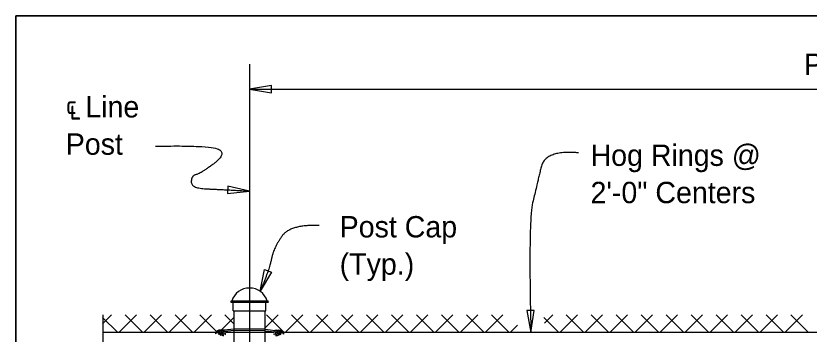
# Model space of a CAD drawing. Extents: x 0 to 41.2, y 0 to 26.
# Drawn here: x 0 to 7.49, y 22.96 to 25.96 of the extents above; entities that cross this region are included whole.
import ezdxf

# ---------------------------------------------------------------- set-up
doc = ezdxf.new("R2010")
doc.units = 0
for name, color, linetype in [('ActivePts-ConstElements', 7, 'Continuous'), ('CL_Major', 7, 'Continuous'), ('Dimension', 7, 'Continuous'), ('Miscellaneous', 7, 'Continuous'), ('Miscellaneous1', 7, 'Continuous'), ('SteelMisc', 7, 'Continuous'), ('SteelMisc_h', 7, 'Continuous'), ('TextStructures', 7, 'Continuous')]:
    doc.layers.add(name, color=color, linetype=linetype)

msp = doc.modelspace()

# ---------------------------------------------------------------- linework, layer by layer
at = {"layer": 'ActivePts-ConstElements'}
msp.add_lwpolyline([(0, 0), (41.2106, 0), (41.2106, 25.96), (0, 25.96)], close=True, dxfattribs=at)
at = {"layer": 'CL_Major'}
msp.add_line((2.2062, 25.5043), (2.2062, 14.6639), dxfattribs=at)
at = {"layer": 'Dimension'}
msp.add_line((2.2062, 25.2672), (22.2062, 25.2672), dxfattribs=at)
for points in [[(2.2062, 25.2672), (2.4145, 25.2319), (2.4145, 25.3025)], [(2.2062, 24.3062), (2.0002, 24.3528), (1.9964, 24.2823)], [(2.3061, 23.3596), (2.3482, 23.5666), (2.414, 23.5412)], [(4.8623, 22.9695), (4.8931, 23.1785), (4.8225, 23.177)]]:
    msp.add_lwpolyline(points, close=True, dxfattribs=at)
msp.add_lwpolyline([(0.8194, 23.1382), (0.8194, 21.1819), (0.9227, 21.1819), (0.8194, 21.1369), (0.716, 21.0919), (0.8194, 21.0919), (0.8194, 20.1983)], dxfattribs=at)
for points in [[(1.3166, 24.7299), (1.8624, 24.7397), (1.9848, 24.6508), (1.7406, 24.4695), (1.6558, 24.4512), (1.6558, 24.3333), (1.9338, 24.321), (2.2061, 24.3061)], [(5.3115, 24.667), (4.9982, 24.6953), (4.9198, 24.3731), (4.8367, 24.0148), (4.8622, 22.9695)], [(2.8646, 23.9801), (2.5898, 23.9929), (2.4301, 23.7626), (2.3965, 23.5753), (2.3061, 23.3596)]]:
    msp.add_open_spline(points, degree=2, dxfattribs=at)
at = {"layer": 'Miscellaneous'}
for p, q in [((0.9027, 23.1361), (0.8192, 23.0527)), ((0.9619, 22.9695), (0.8192, 23.1121)), ((1.1384, 23.1361), (0.9717, 22.9695)), ((1.1976, 22.9695), (1.0309, 23.1361)), ((1.3741, 23.1361), (1.2074, 22.9695)), ((1.4333, 22.9695), (1.2666, 23.1361)), ((1.6098, 23.1361), (1.4431, 22.9695)), ((1.669, 22.9695), (1.5023, 23.1361)), ((1.8455, 23.1361), (1.6788, 22.9695)), ((1.8932, 22.981), (1.738, 23.1361)), ((2.0603, 23.1153), (1.9381, 22.993)), ((2.0603, 23.0495), (1.9737, 23.1361)), ((2.4746, 23.1361), (2.352, 23.0136)), ((2.5338, 22.9695), (2.3671, 23.1361)), ((2.7103, 23.1361), (2.5436, 22.9695)), ((2.7695, 22.9695), (2.6028, 23.1361)), ((2.946, 23.1361), (2.7793, 22.9695)), ((3.0052, 22.9695), (2.8385, 23.1361)), ((3.1817, 23.1361), (3.015, 22.9695)), ((3.2409, 22.9695), (3.0742, 23.1361)), ((3.4174, 23.1361), (3.2507, 22.9695)), ((3.4766, 22.9695), (3.3099, 23.1361)), ((3.6531, 23.1361), (3.4864, 22.9695)), ((3.7123, 22.9695), (3.5456, 23.1361)), ((3.8888, 23.1361), (3.7221, 22.9695)), ((3.948, 22.9695), (3.7813, 23.1361)), ((4.1245, 23.1361), (3.9578, 22.9695)), ((4.1837, 22.9695), (4.017, 23.1361)), ((4.3602, 23.1361), (4.1935, 22.9695)), ((4.4194, 22.9695), (4.2527, 23.1361)), ((4.5959, 23.1361), (4.4292, 22.9695)), ((4.6551, 22.9695), (4.4884, 23.1361)), ((5.1265, 22.9695), (4.9846, 23.1113)), ((5.0673, 23.1361), (4.991, 23.0599)), ((5.303, 23.1361), (5.1363, 22.9695)), ((5.3622, 22.9695), (5.1955, 23.1361)), ((5.5387, 23.1361), (5.372, 22.9695)), ((5.5979, 22.9695), (5.4312, 23.1361)), ((5.7744, 23.1361), (5.6077, 22.9695)), ((5.8336, 22.9695), (5.6669, 23.1361)), ((6.0101, 23.1361), (5.8434, 22.9695)), ((6.0693, 22.9695), (5.9026, 23.1361)), ((6.2458, 23.1361), (6.0791, 22.9695)), ((6.305, 22.9695), (6.1383, 23.1361)), ((6.4815, 23.1361), (6.3148, 22.9695)), ((6.5407, 22.9695), (6.374, 23.1361)), ((6.7172, 23.1361), (6.5505, 22.9695)), ((6.7764, 22.9695), (6.6097, 23.1361)), ((6.9529, 23.1361), (6.7862, 22.9695)), ((7.0121, 22.9695), (6.8455, 23.1361)), ((7.1886, 23.1361), (7.0219, 22.9695)), ((7.2478, 22.9695), (7.0812, 23.1361)), ((7.4243, 23.1361), (7.2576, 22.9695)), ((7.4835, 22.9695), (7.3169, 23.1361)), ((4.7358, 23.0403), (4.6649, 22.9695)), ((1.9047, 22.9695), (1.9002, 22.9739)), ((4.8908, 22.9695), (4.8908, 22.9695))]:
    msp.add_line(p, q, dxfattribs=at)
at = {"layer": 'Miscellaneous1'}
msp.add_lwpolyline([(0, 25.96), (41.2106, 25.96), (41.2106, 0), (0, 0)], close=True, dxfattribs=at)
at = {"layer": 'SteelMisc'}
for p, q in [((2.3786, 23.2681), (2.034, 23.2681)), ((2.034, 23.2559), (2.3786, 23.2559)), ((2.0522, 23.1761), (2.0522, 23.2559)), ((2.3603, 23.1761), (2.3603, 23.2559)), ((2.0522, 23.1761), (2.3603, 23.1761)), ((2.0603, 17.5309), (2.0603, 23.1761)), ((2.352, 17.5309), (2.352, 23.1761)), ((2.0608, 23.0038), (1.9665, 22.9926)), ((2.0608, 22.9892), (1.9687, 22.9798)), ((2.352, 23.0021), (2.0608, 23.0038)), ((2.352, 22.9876), (2.0608, 22.9892)), ((2.352, 23.0021), (2.4469, 22.991)), ((1.8859, 22.9695), (0.8192, 22.9695)), ((1.9096, 22.9695), (1.8943, 22.9695)), ((2.0603, 22.9695), (1.9799, 22.9695)), ((2.352, 22.9876), (2.4446, 22.978)), ((2.4342, 22.9695), (2.352, 22.9695)), ((2.5172, 22.9695), (2.5041, 22.9695)), ((11.923, 22.9695), (2.5271, 22.9695))]:
    msp.add_line(p, q, dxfattribs=at)
for centre, start, end in [((2.034, 23.2618), 91.1647, 268.8353), ((2.3783, 23.2618), 271.1647, 88.8353)]:
    msp.add_arc(centre, 0.00613, start, end, dxfattribs=at)
for centre, major_axis, ratio, start_param, end_param in [((2.2055, 23.227), (-0.1711, 0), 0.957868, 3.394611, 6.030583), ((1.9209, 22.957), (0.0373, 0), 0.957868, 1.486836, 3.108042), ((1.9333, 22.9714), (0.023, 0), 0.957868, 1.29026, 2.970541), ((1.9521, 22.9661), (0.0295, 0), 0.957868, 1.220941, 4.039556), ((1.9656, 22.9678), (-0.0303, -0.0108), 0.724765, 4.35367, 6.324556), ((2.4482, 22.9661), (0.0303, -0.0108), 0.724765, 6.241815, 8.212701), ((2.4617, 22.9643), (-0.0295, 0), 0.957868, 2.243629, 5.062245), ((2.4804, 22.9697), (-0.023, 0), 0.957868, 3.312645, 4.992926), ((2.4929, 22.9552), (-0.0373, 0), 0.957868, 3.175144, 4.79635), ((1.942, 22.9173), (-0.0724, 0), 0.957868, 5.162149, 5.652106), ((1.9345, 22.9689), (-0.0249, 0), 0.957868, 6.009018, 7.089857), ((1.9554, 22.9592), (0.0206, -0.0021), 0.798607, 3.333154, 5.220153), ((1.9623, 22.9638), (-0.0139, 0), 0.957868, 5.22362, 6.905413), ((1.9566, 22.9614), (-0.00795, 0), 0.957868, 6.140374, 9.314262), ((1.9706, 22.9549), (-0.0259, 0), 0.957868, 4.777514, 5.62749), ((1.9549, 22.9672), (0.0119, 0), 0.957868, 5.725876, 7.416677), ((1.9549, 22.9672), (0.0119, 0), 0.957868, 5.639684, 5.723117), ((1.9551, 22.966), (0.0251, 0), 0.957868, 5.531357, 6.227833), ((1.9551, 22.966), (0.0251, 0), 0.957868, 0.407687, 0.609214), ((2.4586, 22.9642), (-0.0251, 0), 0.957868, 0.055352, 0.751829), ((2.4586, 22.9642), (-0.0251, 0), 0.957868, 5.673972, 5.875498), ((2.4431, 22.9532), (0.0259, 0), 0.957868, 0.655696, 1.505671), ((2.4589, 22.9654), (-0.0119, 0), 0.957868, 5.149694, 6.840495), ((2.4589, 22.9654), (-0.0119, 0), 0.957868, 0.560069, 0.643501), ((2.4572, 22.9596), (0.00795, 0), 0.957868, 3.252108, 6.425997), ((2.4583, 22.9575), (-0.0206, -0.0021), 0.798607, 1.063032, 2.950031), ((2.4515, 22.962), (0.0139, 0), 0.957868, 5.660958, 7.342751), ((2.4793, 22.9671), (0.0249, 0), 0.957868, 5.476514, 6.557353), ((2.4718, 22.9155), (0.0724, 0), 0.957868, 0.631079, 1.121037)]:
    msp.add_ellipse(centre, major_axis=major_axis, ratio=ratio, start_param=start_param, end_param=end_param, dxfattribs=at)
at = {"layer": 'SteelMisc_h'}
msp.add_line((2.352, 22.9695), (2.0603, 22.9695), dxfattribs=at)

# ---------------------------------------------------------------- texts
at = {"layer": 'Dimension'}
for s, p in [('℄ Line ', (0.4712, 25.0009)), ('Post', (0.4712, 24.6489)), ('Hog Rings @ ', (5.4249, 24.5436)), ('2\'-0" Centers', (5.4249, 24.1916)), ('Post Cap ', (3.0566, 23.8683)), ('(Typ.)', (3.0566, 23.5163))]:
    msp.add_text(s, height=0.2016, dxfattribs=at).set_placement(p)
at = {"layer": 'TextStructures'}
msp.add_text('Pull Post Assembly (required at maximum intervals of 500\'-0")', height=0.2016, dxfattribs=at).set_placement((7.4383, 25.402))

doc.saveas('drawing.dxf')
